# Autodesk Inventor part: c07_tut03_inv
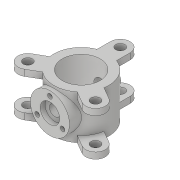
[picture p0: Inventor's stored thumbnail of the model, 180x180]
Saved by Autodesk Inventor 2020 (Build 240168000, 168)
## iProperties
Created: 2017-04
Part Number: c07_tut03_inv
Material: Generic
Document SubType Name: Modeling
Designer: CADCIM 00
Density: 1 g/cm^3
Appearance: Default
Author: CADCIM 00
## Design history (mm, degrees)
sketch "Sketch1"
  geometry: C1 r 140 at (0, 0); C2 r 97 at (0, 0); 1 further point
  constraints: 2 centre point, 2 coincident
  dimensions: "d0" = 280 diameter of C1; "d1" = 194 diameter of C2
extrude "Extrusion1" new body sketch "Sketch1" stored distance "d2" = 225; taper "d3" = 0 deg
workplane "Work Plane1"
sketch "Sketch2"
  geometry: C1 r 100 at (0, 0); 1 further point
  constraints: 1 centre point, 1 coincident
  dimensions: "d5" = 200 diameter of C1
extrude "Extrusion2" join sketch "Sketch2" stored distance "d6" = 225; taper "d7" = 0 deg
workplane "Work Plane2"
sketch "Sketch3"
  geometry: C1 r 37.5 at (0, 0); 1 further point
  constraints: 1 centre point, 1 coincident
  dimensions: "d9" = 75 diameter of C1
extrude "Extrusion3" join sketch "Sketch3" stored distance "d10" = 225; taper "d11" = 0 deg
hole "Hole1" diameter "d14" = 56; stored, may be unused: countersink angle "d18" = 90 deg, drill point angle "d20" = 0 deg; dims "d12" = 10, "d13" = 10, "d15" = 6, "d16" = 100, "d17" = 25, "d19" = 310
sketch "Sketch6"
  geometry: 2 further points
  constraints: 1 vertical alignment
  dimensions: "d21" = 75 distance of point (0, 75) point (0, 0)
hole "Hole2" sketch "Sketch6" at (0, 75) diameter "d22" = 24; stored, may be unused: countersink angle "d26" = 90 deg, drill point angle "d28" = 0 deg; dims "d23" = 6, "d24" = 100, "d25" = 25, "d27" = 15
pattern_circular "Circular Pattern1" dims angle "d30" = 360 deg
sketch "Sketch7"
  geometry: L1 (-50, 130.767)-(-50, 200); L2 (50, 200)-(50, 130.767); L3 (0, 0)-(0, 200); C1 r 23.5 at (0, 200); A1 r 50 centre (0, 200) between (50, 200) and (-50, 200); A2 r 140 centre (0, 0) between (-50, 130.767) and (50, 130.767) reference; 1 further point
  constraints: 6 end point, 4 point on circle, 2 centre point, 2 tangent, 2 vertical, 1 coincident, 1 parallel
  dimensions: "d32" = 200 distance of point (0, 0) L3.end; "d34" = 47 diameter of C1; "d40" = 50 radius of A1
extrude "Extrusion4" join sketch "Sketch7" distance "d35" = 32; taper "d36" = 0 deg
pattern_circular "Circular Pattern2" dims angle "d38" = 360 deg
mirror "Mirror1"
body "Solid1"
other parameters: "d8" = 325
